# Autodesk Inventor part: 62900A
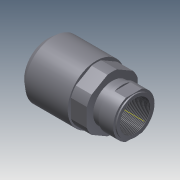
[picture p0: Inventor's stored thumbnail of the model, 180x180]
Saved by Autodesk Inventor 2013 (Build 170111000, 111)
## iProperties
Shininess: 25.0
Length Units: 11269
Angle Units: 11279
Time Units: 11290
Mass Units: 11283
Length Display Precision: 3
Angle Display Precision: 2
Created: 2002-07
Part Number: 62900A
Document SubType Name: Modeling
Designer: SaAlex
Material: Steel, Mild
Density: 7.86 g/cm^3
Density: 0.0
Volumn: 0.0
Area: 0.0
PropertySet Name: Model Information
Control State: 0
Master: False
Checked Out: False
Checked Out Date: 2008-10-15
Last Check In Date: 2008-10-15
Author: SaAlex
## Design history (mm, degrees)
sketch "Sketch1"
  geometry: L1 (-67, 45)-(0, 45); L2 (-77, 36.5)-(-67, 45); L3 (-77, 36.5)-(-77, 32.5); L4 (-79, 32.5)-(-77, 32.5); L5 (-79, 30)-(-79, 32.5); L6 (-81, 30)-(-79, 30); L7 (-81, 0)-(-81, 30); L8 (-81, 0)-(0, 0); L9 (0, 45)-(0, 0); L10 (-81, 0)-(0, 0)
  constraints: 20 end point, 4 horizontal, 3 vertical, 1 other
  dimensions: "d67" = 81 distance between parallel lines of L9 L7; "d68" = 2 distance between parallel lines of L5 L7; "d69" = 2 distance between parallel lines of L3 L5; "d70" = 14 distance from line of L1.start L7; "d71" = 30 distance between parallel lines of L8 L6; "d72" = 32.5 distance between parallel lines of L8 L4; "d73" = 36.5 distance from line of L8 L2.start; "d75" = 45 distance from line of L8 L1.start
revolve "RevolutionFull1" sketch "Sketch1" stored, may be unused: angle "d0" = 360 deg
sketch "Sketch2"
  geometry: L1 (41.822, 7.563)-(27.46, 32.437); L2 (27.46, -32.437)-(41.822, -7.563); L3 (-14.361, -40)-(14.361, -40); L4 (-41.822, -7.563)-(-27.46, -32.437); L5 (-27.46, 32.437)-(-41.822, 7.563); L6 (14.361, 40)-(-14.361, 40); C1 r 40 at (0, 0); C2 r 45 at (0, 0) reference; A1 r 42.5 centre (0, 0) between (41.822, -7.563) and (41.822, 7.563); A2 r 42.5 centre (0, 0) between (14.361, -40) and (27.46, -32.437); A3 r 42.5 centre (0, 0) between (-27.46, -32.437) and (-14.361, -40); A4 r 42.5 centre (0, 0) between (-41.822, 7.563) and (-41.822, -7.563); A5 r 42.5 centre (0, 0) between (-14.361, 40) and (-27.46, 32.437); A6 r 42.5 centre (0, 0) between (27.46, 32.437) and (14.361, 40)
  constraints: 12 end point, 12 point on circle, 8 concentric, 7 centre point, 6 tangent, 2 horizontal, 1 coincident, 1 parallel
  dimensions: "d4" = 80 diameter of C1; "d6" = 42.5 radius of A5
extrude "ExtrusionBlind1" join sketch "Sketch2" distance "d7" = 25; taper "d8" = 0 deg
sketch "Sketch3"
  geometry: L1 (-29, 0)-(21, 0)
  constraints: 2 end point
node "WorkAxis1"
sketch "Sketch4"
  geometry: L1 (-25, 0)-(-36, 0); L2 (-25, 30)-(-25, 0); L3 (-36, 30)-(-25, 30); L4 (-36, 0)-(-36, 30); L5 (-25, -42.5)-(-25, -41.822) reference; L6 (-25, 0)-(-36, 0); L7 (104.4, 0)-(-59.4, 0) reference
  constraints: 10 end point, 2 collinear, 2 horizontal, 2 vertical
  dimensions: "d12" = 11 distance of L3.start L2.start; "d14" = 60 diameter of L3.start L1
revolve "RevolutionFull2" sketch "Sketch4" stored, may be unused: angle "d15" = 360 deg
sketch "Sketch5"
  geometry: L1 (-36, 0)-(-41, 0); L2 (-36, 32.5)-(-36, 0); L3 (-41, 32.5)-(-36, 32.5); L4 (-41, 0)-(-41, 32.5); L5 (-36, -30)-(-36, 30) reference; L6 (-36, 0)-(-41, 0)
  constraints: 10 end point, 2 horizontal, 2 vertical, 1 collinear
  dimensions: "d17" = 5 distance of L3.start L2.start; "d19" = 65 diameter of L3.start L1
revolve "RevolutionFull3" sketch "Sketch5" stored, may be unused: angle "d20" = 360 deg
sketch "Sketch6"
  geometry: L1 (41, 32.5)-(41, 0); L2 (59, 32.5)-(41, 32.5); L3 (59, 0)-(59, 32.5); L4 (41, 0)-(59, 0); L5 (41, 32.5)-(41, -32.5) reference; L6 (-92.53, 0)-(84.53, 0); L7 (41, 0)-(59, 0)
  constraints: 12 end point, 2 collinear, 2 horizontal, 2 vertical
  dimensions: "d23" = 32.5 distance of L3.start L2.start; "d25" = 18 distance of L2.start L5.start
revolve "RevolutionFull4" sketch "Sketch6" stored, may be unused: angle "d26" = 360 deg
sketch "Sketch7"
  geometry: L1 (-30, -37.13)-(-40, -37.13); L2 (-30, 22.87)-(-30, -37.13); L3 (-40, 22.87)-(-30, 22.87); L4 (-40, -37.13)-(-40, 22.87); C1 r 30 at (0, 0) reference
  constraints: 8 end point, 2 horizontal, 2 vertical
  dimensions: "d31" = 30 horizontal distance of L2.start C1.centre; "d33" = 60 distance of L1.end L3.start; "d35" = 10 distance of L1.start L1.end
extrude "ExtrusionBlind2" cut sketch "Sketch7" distance "d36" = 18; taper "d37" = 0 deg
pattern_circular "PolarArray1" dims angle "d40" = 360 deg
sketch "Sketch9"
  geometry: L1 (59, 29)-(59, 0); L2 (61, 29)-(59, 29); L3 (61, 0)-(61, 29); L4 (59, 0)-(61, 0); L5 (59, 12.5)-(59, 32.5) reference; L6 (-92.53, 0)-(84.53, 0); L7 (59, 0)-(61, 0)
  constraints: 12 end point, 2 collinear, 2 horizontal, 2 vertical
  dimensions: "d45" = 2 distance of L1.end L3.start; "d47" = 29 distance of L3.start L2.start
revolve "RevolutionFull6" sketch "Sketch9" stored, may be unused: angle "d48" = 360 deg
sketch "Sketch10"
  geometry: C1 r 30 at (0, 0) reference
hole "Hole1" sketch "Sketch10" diameter "d49" = 48; stored, may be unused: countersink angle "d53" = 82 deg, drill point angle "d55" = 120 deg; dims "d50" = 35, "d51" = 4, "d52" = 2, "d54" = 40
sketch "Sketch11"
  geometry: C1 r 29 at (0, 0) reference; 1 further point
hole "Hole2" sketch "Sketch11" at (0, 0) diameter "d57" = 48; stored, may be unused: countersink angle "d61" = 82 deg, drill point angle "d63" = 120 deg; dims "d58" = 35, "d59" = 4, "d60" = 2, "d62" = 40
feature "Резьба1" dims "d76" = 10, "d77" = 0
feature "Резьба2" dims "d78" = 10, "d79" = 0
sketch "Sketch12"
  geometry: L1 (0, 28.723)-(0, 0) reference; L2 (25, 28.723)-(0, 28.723) reference; L3 (5, 15.723)-(20, 15.723); L4 (20, 15.723)-(20, 17.223); L5 (20, 17.223)-(24.289, 15.223); L6 (24.289, 15.223)-(20, 13.223); L7 (20, 13.223)-(20, 14.723); L8 (20, 14.723)-(5, 14.723); L9 (5, 14.723)-(5, 15.723); L10 (8, 17.723)-(8.325, 18.103); L11 (14.325, 18.103)-(14.713, 17.772); L12 (5, 15.223)-(24.289, 15.223); L13 (14.325, 12.343)-(14.713, 12.674); L14 (8, 12.723)-(8.325, 12.343); A1 r 5.499 centre (11.325, 22.103) between (8, 17.723) and (14.713, 17.772); A2 r 5 centre (11.325, 22.103) between (8.325, 18.103) and (14.325, 18.103); A3 r 5 centre (11.325, 8.343) between (14.325, 12.343) and (8.325, 12.343); A4 r 5.499 centre (11.325, 8.343) between (14.713, 12.674) and (8, 12.723)
  constraints: 24 end point, 8 point on circle, 5 symmetric about line, 4 centre point, 3 parallel, 2 perpendicular, 1 collinear, 1 midpoint, 2 other
  dimensions: "d80" = 1 distance between parallel lines of L3 L8; "d81" = 13 distance between parallel lines of L2 L3; "d82" = 5 distance between parallel lines of L1 L9; "d83" = 15 distance between parallel lines of L7 L9; "d84" = 4 distance of L4.end L6.end; "d85" = 1.5 distance from line of L8 L6.end; "d86" = 2 vertical distance of L6.end L5.end; "d87" = 50 deg angle of L5 L6; "d88" = 0 distance between parallel lines of L4 L7; "d89" = 0.5 distance of L10.start L10.end; "d90" = 5 radius of A2; "d91" = 0 vertical distance of L10.end L11.start; "d92" = 2 distance from line of L10.start L3; "d93" = 3 horizontal distance of L10.start L3.start; "d94" = 6 distance of L11.start L10.end
extrude "Extrusion3" cut sketch "Sketch12" distance "d95" = 0.5; taper "d96" = 0 deg
body "Solid1"
other parameters: "d1" = 0, "d2" = 0, "d5" = 42.5 (derived), "d9" = 0, "d10" = 0, "d11" = 11 (derived), "d16" = 5 (derived), "d18" = 65 (derived), "d21" = 0, "d22" = 32.5 (derived), "d24" = 18 (derived), "d27" = 0, "d28" = 0, "d29" = 0, "d41" = 2 (derived), "d44" = 2 (derived), "d46" = 29 (derived), "d56" = 0
